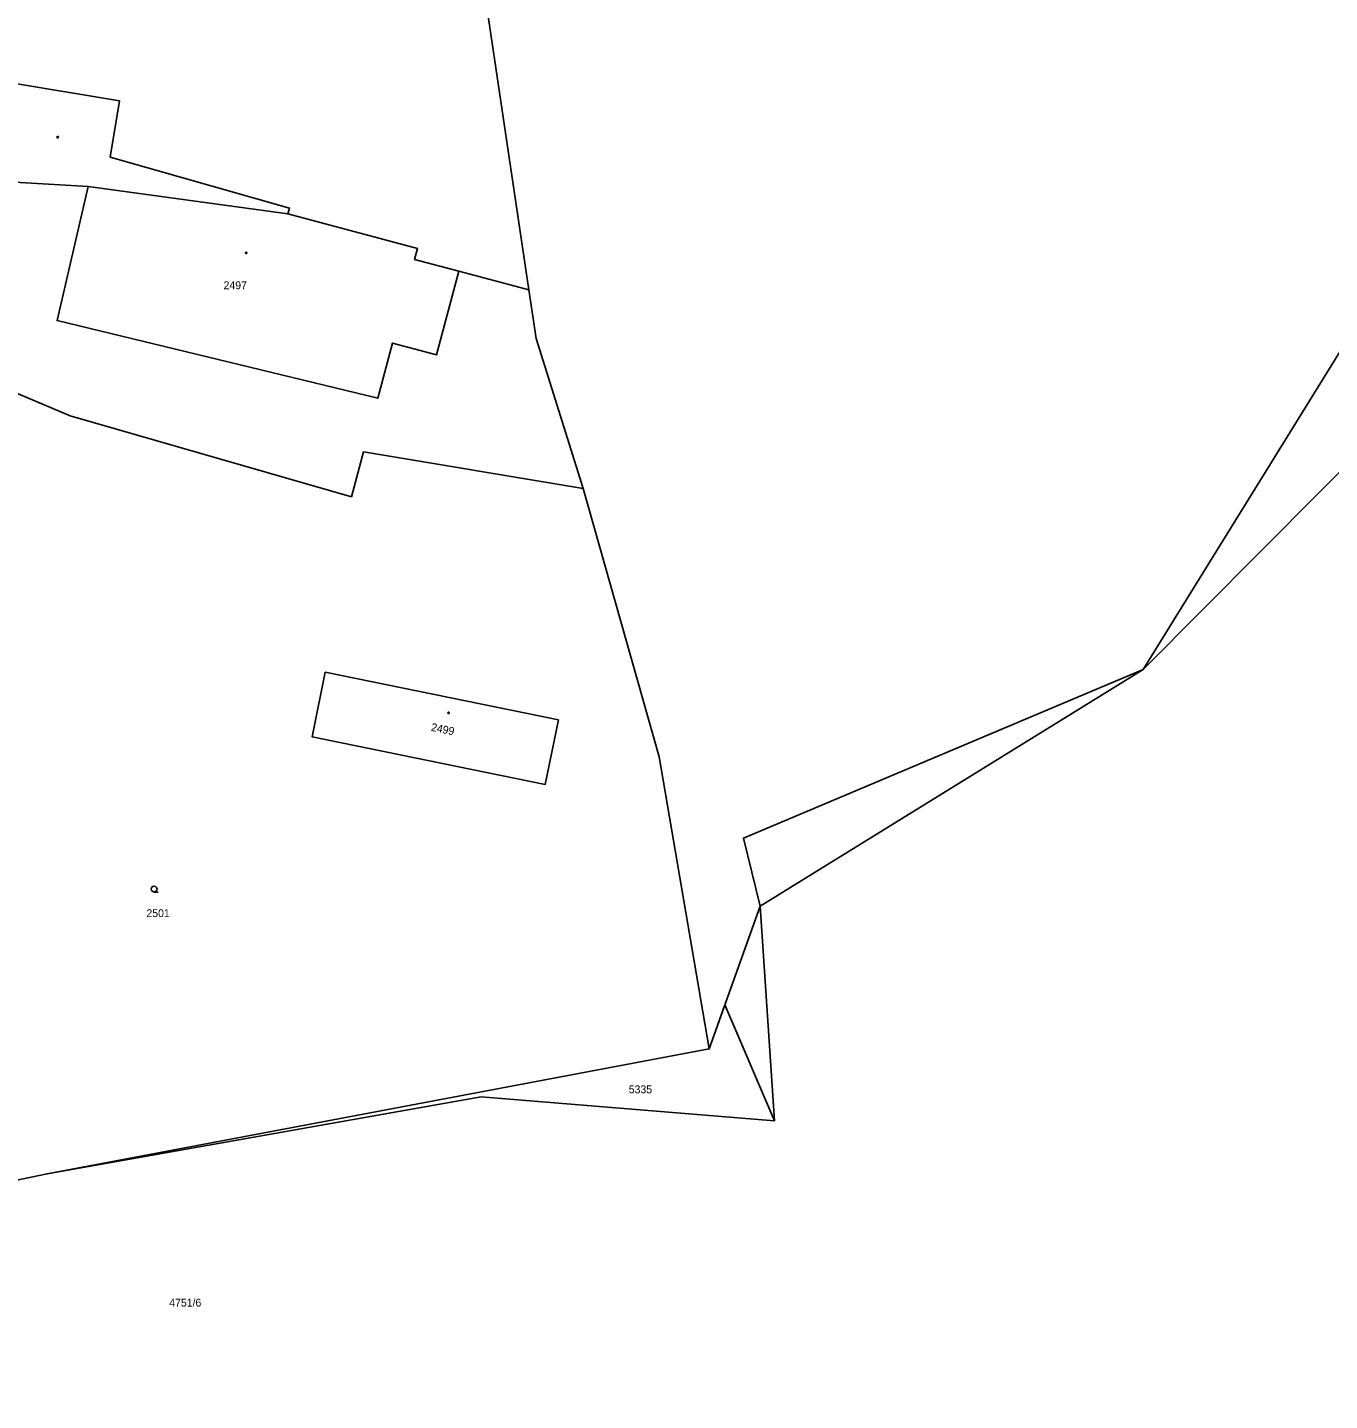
# Model space of a CAD drawing. Extents: x -439750 to -439180, y -1258684 to -1258308.
# Drawn here: x -439377.6 to -439311.2, y -1258499.7 to -1258429.7 of the extents above; entities that cross this region are included whole.
import ezdxf

# ---------------------------------------------------------------- set-up
doc = ezdxf.new("R2010")
doc.units = 0
doc.layers.add('KATASTER', color=7, linetype='Continuous')
doc.layers.add('UOV', color=7, linetype='Continuous')

# ---------------------------------------------------------------- blocks, each defined once
blk = doc.blocks.new('402')
blk.add_lwpolyline([(0.09, 0.15), (0.18, 0), (0.09, -0.15), (-0.09, -0.15), (-0.18, 0), (-0.09, 0.15), (0.09, 0.15)])
blk = doc.blocks.new('304')
blk.add_lwpolyline([(0, 0), (-0.38, 0.1), (-0.65, 0.37), (-0.75, 0.74), (-0.65, 1.11), (-0.38, 1.38), (-0.01, 1.48), (0.36, 1.38), (0.63, 1.11), (0.73, 0.73), (0.63, 0.35), (0.36, 0.08), (-0.02, -0.02), (0.98, -0.02)])

msp = doc.modelspace()

# ---------------------------------------------------------------- linework, layer by layer
at = {"layer": 'KATASTER'}
for p, q in [((-439374.5, -1258437.8), (-439364.32, -1258439.2)), ((-439344.03, -1258474.81), (-439342.84, -1258481.76))]:
    msp.add_line(p, q, dxfattribs=at)
for points in [[(-439342.84, -1258481.76), (-439376.6, -1258488.12), (-439398.93, -1258492.76), (-439393.11, -1258458.67), (-439387.21, -1258424.13), (-439355.89, -1258417.18), (-439355.78, -1258417.92), (-439352.04, -1258443.07), (-439355.61, -1258442.12), (-439357.86, -1258441.52), (-439357.71, -1258440.96), (-439364.32, -1258439.2), (-439364.24, -1258438.91), (-439373.38, -1258436.31), (-439372.9, -1258433.44), (-439378.54, -1258432.5), (-439378.83, -1258437.55), (-439380.62, -1258447.31), (-439375.42, -1258449.5)], [(-439355.61, -1258442.12), (-439356.74, -1258446.39), (-439358.99, -1258445.79), (-439359.74, -1258448.6), (-439376.09, -1258444.64), (-439374.5, -1258437.8), (-439378.83, -1258437.55)], [(-439301.47, -1258497.62), (-439327.16, -1258518.51), (-439334.67, -1258520.03), (-439347.2, -1258516.43), (-439344.2, -1258505.65), (-439348.78, -1258505.65), (-439378.69, -1258503.81), (-439387.09, -1258499.74), (-439400.54, -1258499.28), (-439399.97, -1258496.98), (-439399.2, -1258493.87), (-439398.93, -1258492.76), (-439376.6, -1258488.12), (-439342.84, -1258481.76), (-439340.24, -1258474.48), (-439320.71, -1258462.43), (-439302.65, -1258444.27)], [(-439375.42, -1258449.5), (-439361.08, -1258453.62), (-439360.47, -1258451.33), (-439349.26, -1258453.19)], [(-439349.26, -1258453.19), (-439345.39, -1258466.88), (-439344.03, -1258474.81)]]:
    msp.add_lwpolyline(points, dxfattribs=at)
for points in [[(-439349.26, -1258453.19), (-439360.47, -1258451.33), (-439361.08, -1258453.62), (-439375.42, -1258449.5), (-439380.62, -1258447.31), (-439378.83, -1258437.55), (-439378.54, -1258432.5), (-439372.9, -1258433.44), (-439373.38, -1258436.31), (-439364.24, -1258438.91), (-439364.32, -1258439.2), (-439357.71, -1258440.96), (-439357.86, -1258441.52), (-439355.61, -1258442.12), (-439352.04, -1258443.07), (-439351.67, -1258445.55)], [(-439362.42, -1258462.56), (-439350.53, -1258464.99), (-439351.2, -1258468.28), (-439363.09, -1258465.85)], [(-439351.2, -1258468.28), (-439350.53, -1258464.99), (-439362.42, -1258462.56), (-439363.09, -1258465.85)]]:
    msp.add_lwpolyline(points, close=True, dxfattribs=at)
at = {"layer": 'UOV'}
msp.add_lwpolyline([(-439301.47, -1258497.62), (-439327.16, -1258518.51), (-439334.67, -1258520.03), (-439347.2, -1258516.43), (-439344.2, -1258505.65), (-439348.78, -1258505.65), (-439370.33, -1258504.32), (-439377.96, -1258500.33), (-439383.83, -1258501.32), (-439387.09, -1258499.74), (-439390.58, -1258499.62), (-439398.93, -1258492.76), (-439376.6, -1258488.12), (-439354.47, -1258484.21), (-439339.52, -1258485.43), (-439340.24, -1258474.48), (-439341.1, -1258471.01), (-439320.71, -1258462.43), (-439304.86, -1258436.82)], dxfattribs=at)
msp.add_lwpolyline([(-439376.6, -1258488.12), (-439342.84, -1258481.76), (-439342.04, -1258479.51), (-439339.52, -1258485.43), (-439354.47, -1258484.21)], close=True, dxfattribs=at)

# ---------------------------------------------------------------- block references
at = {"layer": 'KATASTER', "xscale": 0.2, "yscale": 0.20000000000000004}
for name, p in [('402', (-439376.06, -1258435.29)), ('402', (-439366.45, -1258441.19)), ('402', (-439356.13, -1258464.63)), ('304', (-439371.14, -1258473.76))]:
    msp.add_blockref(name, p, dxfattribs=at)

# ---------------------------------------------------------------- texts
at = {"layer": 'KATASTER'}
for s, p in [('2497', (-439367.602, -1258443.04)), ('2501', (-439371.535, -1258475.04))]:
    msp.add_text(s, height=0.4, dxfattribs=at).set_placement(p)
msp.add_text('2499', height=0.4, rotation=348.244, dxfattribs=at).set_placement((-439357.048, -1258465.538))
at = {"layer": 'UOV'}
for s, p in [('5335', (-439346.944, -1258484.02)), ('4751/6', (-439370.372, -1258494.892))]:
    msp.add_text(s, height=0.4, dxfattribs=at).set_placement(p)

doc.saveas('drawing.dxf')
